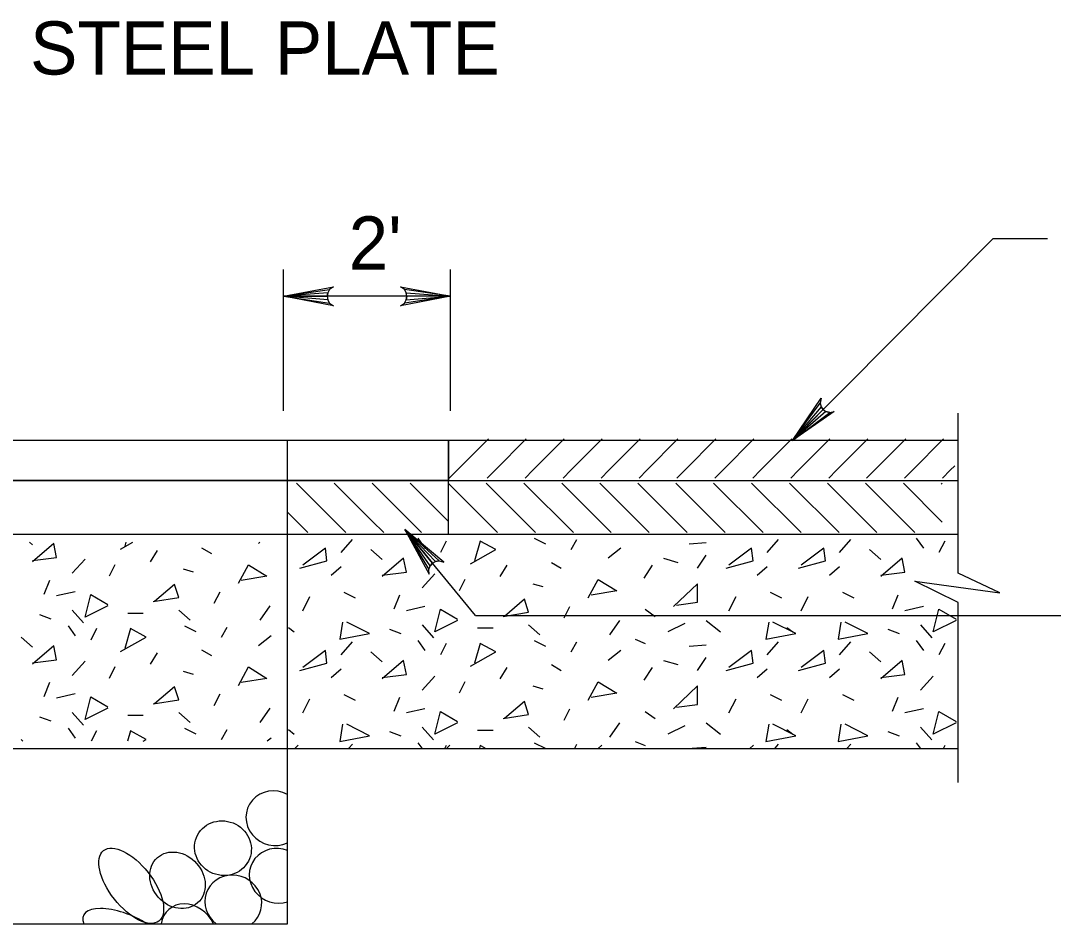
# Model space of a CAD drawing. Extents: x 3.47 to 10.73, y 1.11 to 10.92.
# Drawn here: x 7.328 to 8.494, y 8.665 to 9.69 of the extents above; entities that cross this region are included whole.
import ezdxf

# ---------------------------------------------------------------- set-up
doc = ezdxf.new("R2010")
doc.units = 0
for name, color, linetype in [('DETL-DIMS', 7, 'Continuous'), ('DETL-LINE', 7, 'Continuous'), ('DETL-NOTE', 7, 'Continuous'), ('DETL-PATT', 7, 'Continuous')]:
    doc.layers.add(name, color=color, linetype=linetype)

msp = doc.modelspace()

# ---------------------------------------------------------------- linework, layer by layer
at = {"layer": 'DETL-DIMS'}
for p, q in [((8.4258, 9.4439), (8.1994, 9.2162)), ((8.4877, 9.4439), (8.4258, 9.4439)), ((7.6246, 9.2497), (7.6246, 9.4093)), ((7.8132, 9.2497), (7.8132, 9.4093)), ((7.8132, 9.379), (7.6246, 9.379)), ((7.8415, 9.0184), (7.7615, 9.1157)), ((7.8415, 9.0184), (8.513, 9.0184))]:
    msp.add_line(p, q, dxfattribs=at)
for points in [[(7.6246, 9.379), (7.6811, 9.3896), (7.6767, 9.3866), (7.6745, 9.3828), (7.6738, 9.379), (7.6745, 9.3752), (7.6767, 9.3714), (7.6811, 9.3684), (7.6246, 9.379), (7.6767, 9.3714), (7.6745, 9.3752), (7.6246, 9.379), (7.6738, 9.379), (7.6745, 9.3828), (7.6246, 9.379), (7.6767, 9.3866)], [(7.8132, 9.379), (7.7567, 9.3684), (7.7611, 9.3714), (7.7633, 9.3752), (7.764, 9.379), (7.7633, 9.3828), (7.7611, 9.3866), (7.7567, 9.3896), (7.8132, 9.379), (7.7611, 9.3866), (7.7633, 9.3828), (7.8132, 9.379), (7.764, 9.379), (7.7633, 9.3752), (7.8132, 9.379), (7.7611, 9.3714)], [(8.1994, 9.2162), (8.2318, 9.2638), (8.2308, 9.2585), (8.2319, 9.2543), (8.2342, 9.2512), (8.2373, 9.2489), (8.2416, 9.2479), (8.2468, 9.2488), (8.1994, 9.2162), (8.2416, 9.2479), (8.2373, 9.2489), (8.1994, 9.2162), (8.2342, 9.2512), (8.2319, 9.2543), (8.1994, 9.2162), (8.2308, 9.2585)], [(7.7615, 9.1157), (7.7892, 9.0653), (7.7888, 9.0706), (7.7903, 9.0747), (7.7928, 9.0776), (7.7961, 9.0795), (7.8005, 9.0802), (7.8056, 9.0788), (7.7615, 9.1157), (7.8005, 9.0802), (7.7961, 9.0795), (7.7615, 9.1157), (7.7928, 9.0776), (7.7903, 9.0747), (7.7615, 9.1157), (7.7888, 9.0706)]]:
    msp.add_lwpolyline(points, dxfattribs=at)
at = {"layer": 'DETL-LINE'}
for p, q in [((8.3867, 9.0665), (8.3867, 9.2469)), ((5.5382, 9.2166), (8.3867, 9.2166)), ((7.6291, 9.2166), (8.3867, 9.2166)), ((7.6291, 9.1105), (7.6291, 9.2166)), ((7.811, 9.1105), (7.811, 9.2166)), ((5.5382, 9.1711), (8.3867, 9.1711)), ((5.5382, 9.1105), (8.3867, 9.1105)), ((7.6291, 8.6704), (7.6291, 9.1105)), ((8.3867, 8.83), (8.3867, 9.0332)), ((6.2958, 8.8681), (7.6291, 8.8681)), ((6.2958, 8.8681), (7.6291, 8.8681)), ((7.6291, 8.8681), (8.3867, 8.8681)), ((6.2958, 8.6704), (7.6291, 8.6704))]:
    msp.add_line(p, q, dxfattribs=at)
msp.add_lwpolyline([(6.114, 9.2166), (7.811, 9.2166), (7.811, 9.1711), (6.114, 9.1711)], close=True, dxfattribs=at)
msp.add_lwpolyline([(8.3867, 9.0332), (8.3376, 9.0572), (8.4337, 9.0442), (8.3867, 9.0665)], dxfattribs=at)
at = {"layer": 'DETL-PATT'}
for p, q in [((7.8207, 9.1826), (7.856, 9.2179)), ((7.8636, 9.1826), (7.8988, 9.2179)), ((7.9064, 9.1826), (7.9417, 9.2179)), ((7.9493, 9.1826), (7.9845, 9.2179)), ((7.9921, 9.1826), (8.0274, 9.2179)), ((8.035, 9.1826), (8.0702, 9.2179)), ((8.0778, 9.1826), (8.1131, 9.2179)), ((8.1207, 9.1826), (8.156, 9.2179)), ((8.1636, 9.1826), (8.1988, 9.2179)), ((8.2064, 9.1826), (8.2417, 9.2179)), ((8.2493, 9.1826), (8.2845, 9.2179)), ((8.2921, 9.1826), (8.3274, 9.2179)), ((8.335, 9.1826), (8.3702, 9.2179)), ((7.8119, 9.1738), (7.8207, 9.1826)), ((7.8548, 9.1738), (7.8636, 9.1826)), ((7.8976, 9.1738), (7.9064, 9.1826)), ((7.9405, 9.1738), (7.9493, 9.1826)), ((7.9833, 9.1738), (7.9921, 9.1826)), ((8.0262, 9.1738), (8.035, 9.1826)), ((8.069, 9.1738), (8.0778, 9.1826)), ((8.1119, 9.1738), (8.1207, 9.1826)), ((8.1547, 9.1738), (8.1636, 9.1826)), ((8.1976, 9.1738), (8.2064, 9.1826)), ((8.2405, 9.1738), (8.2493, 9.1826)), ((8.2833, 9.1738), (8.2921, 9.1826)), ((8.3262, 9.1738), (8.335, 9.1826)), ((8.369, 9.1738), (8.3778, 9.1826)), ((8.3778, 9.1826), (8.3829, 9.1877)), ((7.6949, 9.1121), (7.6391, 9.168)), ((7.7248, 9.1251), (7.682, 9.168)), ((7.7806, 9.1121), (7.7248, 9.168)), ((7.811, 9.1247), (7.7677, 9.168)), ((7.8664, 9.1121), (7.8105, 9.168)), ((7.9092, 9.1121), (7.8534, 9.168)), ((7.9521, 9.1121), (7.8962, 9.168)), ((7.9949, 9.1121), (7.9391, 9.168)), ((8.0378, 9.1121), (7.982, 9.168)), ((8.0806, 9.1121), (8.0248, 9.168)), ((8.1235, 9.1121), (8.0677, 9.168)), ((8.1663, 9.1121), (8.1105, 9.168)), ((8.2092, 9.1121), (8.1534, 9.168)), ((8.2521, 9.1121), (8.1962, 9.168)), ((8.2949, 9.1121), (8.2391, 9.168)), ((8.3248, 9.1251), (8.2819, 9.168)), ((8.3688, 9.1239), (8.3248, 9.168)), ((8.3688, 9.1668), (8.3677, 9.168)), ((7.6521, 9.1121), (7.6291, 9.1351)), ((7.7378, 9.1121), (7.7248, 9.1251)), ((8.3378, 9.1121), (8.3248, 9.1251)), ((7.3377, 9.1012), (7.341, 9.0983)), ((7.4405, 9.0935), (7.4544, 9.1012)), ((7.4466, 9.1012), (7.4453, 9.0967)), ((7.5978, 9.1012), (7.5962, 9.1)), ((7.6897, 9.0897), (7.7025, 9.1042)), ((7.7763, 9.1058), (7.7844, 9.0945)), ((7.8084, 9.1026), (7.802, 9.0897)), ((7.9079, 9.1058), (7.9207, 9.0993)), ((7.9496, 9.0929), (7.9561, 9.1042)), ((8.0828, 9.0993), (8.1021, 9.101)), ((8.1711, 9.0897), (8.1839, 9.1042)), ((8.2527, 9.0897), (8.2656, 9.1042)), ((8.3394, 9.1058), (8.3474, 9.0945)), ((8.3715, 9.1026), (8.365, 9.0897)), ((7.4742, 9.0791), (7.4823, 9.0919)), ((7.532, 9.0951), (7.5432, 9.0887)), ((7.7234, 9.0929), (7.7362, 9.0817)), ((8.0058, 9.0945), (7.9914, 9.0833)), ((8.2864, 9.0929), (8.2993, 9.0817)), ((7.4004, 9.0823), (7.386, 9.0663)), ((7.4341, 9.0759), (7.4277, 9.063)), ((7.9272, 9.0785), (7.9384, 9.0721)), ((8.0539, 9.0833), (8.07, 9.0785)), ((8.0924, 9.0721), (8.1021, 9.0865)), ((7.5111, 9.0711), (7.5224, 9.0679)), ((7.6785, 9.064), (7.6897, 9.0737)), ((7.7956, 9.0656), (7.7812, 9.0496)), ((7.8694, 9.0624), (7.8774, 9.0753)), ((8.0411, 9.0753), (8.0315, 9.0608)), ((8.1598, 9.064), (8.1711, 9.0737)), ((8.2415, 9.064), (8.2527, 9.0737)), ((7.3603, 9.0582), (7.3539, 9.0422)), ((7.8293, 9.0592), (7.8229, 9.0464)), ((7.9063, 9.0544), (7.9175, 9.0512)), ((7.3892, 9.0454), (7.3683, 9.0406)), ((7.5464, 9.0326), (7.5529, 9.0454)), ((7.6929, 9.0448), (7.7057, 9.0384)), ((7.7555, 9.0416), (7.7491, 9.0255)), ((8.1743, 9.0448), (8.1871, 9.0384)), ((8.2559, 9.0448), (8.2688, 9.0384)), ((8.3185, 9.0416), (8.3121, 9.0255)), ((7.609, 9.0293), (7.5978, 9.0133)), ((7.6464, 9.0239), (7.6544, 9.04)), ((8.1277, 9.0239), (8.1358, 9.04)), ((8.2094, 9.0239), (8.2174, 9.04)), ((7.3491, 9.0197), (7.3619, 9.0149)), ((7.386, 9.0245), (7.3988, 9.0101)), ((7.4486, 9.0213), (7.4662, 9.0213)), ((7.5063, 9.0245), (7.5192, 9.0133)), ((7.7844, 9.0287), (7.7635, 9.0239)), ((7.9416, 9.0159), (7.948, 9.0287)), ((8.0331, 9.0255), (8.0443, 9.0175)), ((8.3474, 9.0287), (8.3265, 9.0239)), ((7.3812, 9.0069), (7.3892, 8.9957)), ((7.5127, 9.0069), (7.5256, 9.0005)), ((7.7812, 9.0079), (7.794, 8.9934)), ((7.9015, 9.0079), (7.9143, 8.9967)), ((8.0042, 9.0127), (7.993, 8.9967)), ((8.078, 9.0095), (8.0587, 8.9999)), ((8.1021, 9.0127), (8.1181, 8.9999)), ((8.3442, 9.0079), (8.357, 8.9934)), ((7.4133, 9.0037), (7.4068, 8.9908)), ((7.5545, 8.994), (7.5609, 9.0053)), ((7.6106, 8.9957), (7.5962, 8.9844)), ((7.6302, 9.0051), (7.6367, 8.9999)), ((7.7442, 9.0031), (7.7571, 8.9983)), ((7.8437, 9.0047), (7.8614, 9.0047)), ((8.1932, 9.0051), (8.1998, 8.9999)), ((8.3073, 9.0031), (8.3201, 8.9983)), ((7.3282, 8.994), (7.341, 8.9828)), ((7.6897, 8.9742), (7.7025, 8.9886)), ((7.7763, 8.9902), (7.7844, 8.979)), ((7.8084, 8.987), (7.802, 8.9742)), ((7.9079, 8.9902), (7.9207, 8.9838)), ((7.9496, 8.9774), (7.9561, 8.9886)), ((8.0218, 8.9918), (8.0331, 8.987)), ((8.0828, 8.9838), (8.1021, 8.9854)), ((8.1711, 8.9742), (8.1839, 8.9886)), ((8.2527, 8.9742), (8.2656, 8.9886)), ((8.3394, 8.9902), (8.3474, 8.979)), ((8.3715, 8.987), (8.365, 8.9742)), ((7.4742, 8.9636), (7.4823, 8.9764)), ((7.532, 8.9796), (7.5432, 8.9732)), ((7.7234, 8.9774), (7.7362, 8.9662)), ((8.0058, 8.979), (7.9914, 8.9678)), ((8.0924, 8.9565), (8.1021, 8.971)), ((8.2864, 8.9774), (8.2993, 8.9662)), ((7.4004, 8.9668), (7.386, 8.9507)), ((7.4341, 8.9604), (7.4277, 8.9475)), ((7.8694, 8.9469), (7.8774, 8.9597)), ((7.9272, 8.963), (7.9384, 8.9565)), ((8.0411, 8.9597), (8.0315, 8.9453)), ((8.0539, 8.9678), (8.07, 8.963)), ((7.5111, 8.9555), (7.5224, 8.9523)), ((7.6785, 8.9485), (7.6897, 8.9581)), ((7.7956, 8.9501), (7.7812, 8.9341)), ((8.1598, 8.9485), (8.1711, 8.9581)), ((8.2415, 8.9485), (8.2527, 8.9581)), ((8.3586, 8.9501), (8.3442, 8.9341)), ((7.3603, 8.9427), (7.3539, 8.9267)), ((7.8293, 8.9437), (7.8229, 8.9309)), ((7.9063, 8.9389), (7.9175, 8.9357)), ((7.3892, 8.9299), (7.3683, 8.9251)), ((7.5464, 8.917), (7.5529, 8.9299)), ((7.6464, 8.9084), (7.6544, 8.9244)), ((7.6929, 8.9293), (7.7057, 8.9228)), ((7.7555, 8.926), (7.7491, 8.91)), ((8.1277, 8.9084), (8.1358, 8.9244)), ((8.1743, 8.9293), (8.1871, 8.9228)), ((8.2094, 8.9084), (8.2174, 8.9244)), ((8.2559, 8.9293), (8.2688, 8.9228)), ((8.3185, 8.926), (8.3121, 8.91)), ((7.609, 8.9138), (7.5978, 8.8978)), ((7.7844, 8.9132), (7.7635, 8.9084)), ((7.9416, 8.9004), (7.948, 8.9132)), ((8.3474, 8.9132), (8.3265, 8.9084)), ((7.3491, 8.9042), (7.3619, 8.8994)), ((7.386, 8.909), (7.3988, 8.8946)), ((7.4486, 8.9058), (7.4662, 8.9058)), ((7.5063, 8.909), (7.5192, 8.8978)), ((8.0331, 8.91), (8.0443, 8.902)), ((7.3812, 8.8914), (7.3892, 8.8801)), ((7.5127, 8.8914), (7.5256, 8.8849)), ((7.5545, 8.8785), (7.5609, 8.8897)), ((7.6302, 8.8896), (7.6367, 8.8843)), ((7.7812, 8.8924), (7.794, 8.8779)), ((7.9015, 8.8924), (7.9143, 8.8811)), ((8.0042, 8.8972), (7.993, 8.8811)), ((8.078, 8.894), (8.0587, 8.8843)), ((8.1021, 8.8972), (8.1181, 8.8843)), ((8.1932, 8.8896), (8.1998, 8.8843)), ((8.3442, 8.8924), (8.357, 8.8779)), ((7.3282, 8.8785), (7.3303, 8.8767)), ((7.4133, 8.8881), (7.4075, 8.8767)), ((7.6106, 8.8801), (7.6062, 8.8767)), ((7.7442, 8.8875), (7.7571, 8.8827)), ((7.8437, 8.8891), (7.8614, 8.8891)), ((8.3073, 8.8875), (8.3201, 8.8827)), ((7.6372, 8.8681), (7.6411, 8.872)), ((7.6985, 8.8686), (7.7025, 8.8731)), ((7.7763, 8.8747), (7.7807, 8.8686)), ((7.8084, 8.8715), (7.807, 8.8686)), ((7.8087, 8.8681), (7.8126, 8.872)), ((7.9079, 8.8747), (7.9202, 8.8686)), ((7.9535, 8.8686), (7.9561, 8.8731)), ((7.9801, 8.8681), (7.984, 8.872)), ((8.0218, 8.8763), (8.0331, 8.8715)), ((8.0864, 8.8686), (8.1021, 8.8699)), ((8.1515, 8.8681), (8.1554, 8.872)), ((8.1799, 8.8686), (8.1839, 8.8731)), ((8.2615, 8.8686), (8.2656, 8.8731)), ((8.3394, 8.8747), (8.3437, 8.8686)), ((8.3715, 8.8715), (8.37, 8.8686))]:
    msp.add_line(p, q, dxfattribs=at)
for points in [[(7.341, 9.0807), (7.3683, 9.0839), (7.3651, 9.1), (7.341, 9.0791)], [(7.8357, 9.0769), (7.8646, 9.0929), (7.8469, 9.1026), (7.8405, 9.0801)], [(7.6432, 9.0721), (7.6736, 9.0801), (7.672, 9.0945), (7.6464, 9.0753)], [(8.1245, 9.0721), (8.155, 9.0801), (8.1534, 9.0945), (8.1277, 9.0753)], [(8.2062, 9.0721), (8.2367, 9.0801), (8.2351, 9.0945), (8.2094, 9.0753)], [(7.5737, 9.055), (7.5849, 9.0759), (7.6058, 9.063), (7.5769, 9.0582)], [(7.7362, 9.064), (7.7635, 9.0673), (7.7603, 9.0833), (7.7362, 9.0624)], [(8.2993, 9.064), (8.3265, 9.0673), (8.3233, 9.0833), (8.2993, 9.0624)], [(7.4774, 9.0342), (7.5063, 9.039), (7.5015, 9.0534), (7.479, 9.0342)], [(7.9689, 9.0384), (7.9801, 9.0592), (8.001, 9.0464), (7.9721, 9.0416)], [(8.0684, 9.0303), (8.0924, 9.0336), (8.0924, 9.0544), (8.0652, 9.0287)], [(7.4261, 9.0293), (7.4004, 9.0165), (7.4068, 9.0422), (7.4261, 9.031)], [(7.8726, 9.0175), (7.9015, 9.0223), (7.8967, 9.0368), (7.8742, 9.0175)], [(7.8213, 9.0127), (7.7956, 8.9999), (7.802, 9.0255), (7.8213, 9.0143)], [(8.3843, 9.0127), (8.3586, 8.9999), (8.365, 9.0255), (8.3843, 9.0143)], [(7.6913, 9.0111), (7.6881, 8.9918), (7.7218, 8.9983), (7.6961, 9.0111)], [(8.1727, 9.0111), (8.1695, 8.9918), (8.2032, 8.9983), (8.1775, 9.0111)], [(8.2543, 9.0111), (8.2511, 8.9918), (8.2848, 8.9983), (8.2591, 9.0111)], [(7.4405, 8.978), (7.4694, 8.994), (7.4518, 9.0037), (7.4453, 8.9812)], [(7.341, 8.9652), (7.3683, 8.9684), (7.3651, 8.9844), (7.341, 8.9636)], [(7.8357, 8.9614), (7.8646, 8.9774), (7.8469, 8.987), (7.8405, 8.9646)], [(7.6432, 8.9565), (7.6736, 8.9646), (7.672, 8.979), (7.6464, 8.9597)], [(8.1245, 8.9565), (8.155, 8.9646), (8.1534, 8.979), (8.1277, 8.9597)], [(8.2062, 8.9565), (8.2367, 8.9646), (8.2351, 8.979), (8.2094, 8.9597)], [(7.5737, 8.9395), (7.5849, 8.9604), (7.6058, 8.9475), (7.5769, 8.9427)], [(7.7362, 8.9485), (7.7635, 8.9517), (7.7603, 8.9678), (7.7362, 8.9469)], [(8.2993, 8.9485), (8.3265, 8.9517), (8.3233, 8.9678), (8.2993, 8.9469)], [(7.4774, 8.9186), (7.5063, 8.9234), (7.5015, 8.9379), (7.479, 8.9186)], [(7.9689, 8.9228), (7.9801, 8.9437), (8.001, 8.9309), (7.9721, 8.926)], [(8.0684, 8.9148), (8.0924, 8.918), (8.0924, 8.9389), (8.0652, 8.9132)], [(7.4261, 8.9138), (7.4004, 8.901), (7.4068, 8.9267), (7.4261, 8.9154)], [(7.8726, 8.902), (7.9015, 8.9068), (7.8967, 8.9212), (7.8742, 8.902)], [(7.8213, 8.8972), (7.7956, 8.8843), (7.802, 8.91), (7.8213, 8.8988)], [(8.3843, 8.8972), (8.3586, 8.8843), (8.365, 8.91), (8.3843, 8.8988)], [(7.6913, 8.8956), (7.6881, 8.8763), (7.7218, 8.8827), (7.6961, 8.8956)], [(8.1727, 8.8956), (8.1695, 8.8763), (8.2032, 8.8827), (8.1775, 8.8956)], [(8.2543, 8.8956), (8.2511, 8.8763), (8.2848, 8.8827), (8.2591, 8.8956)], [(7.4661, 8.8767), (7.4694, 8.8785), (7.4518, 8.8881), (7.4485, 8.8767)], [(7.8523, 8.8686), (7.8469, 8.8715), (7.8461, 8.8686)]]:
    msp.add_lwpolyline(points, dxfattribs=at)
for centre, major_axis, ratio, start_param, end_param in [((7.6143, 8.7895), (-0.03, 0.012), 0.948581, 4.594923, 8.696661), ((7.618, 8.7245), (-0.03, 0.012), 0.948581, 4.719373, 8.572212), ((7.5679, 8.6944), (-0.03, 0.012), 0.948581, 2.649322, 7.573475), ((7.5175, 8.6608), (-0.0227, 0.0256), 0.844245, 4.37248, 6.906237), ((7.4449, 8.6598), (0.0464, -0.0197), 0.422273, 1.177599, 3.53942)]:
    msp.add_ellipse(centre, major_axis=major_axis, ratio=ratio, start_param=start_param, end_param=end_param, dxfattribs=at)
for centre, major_axis, ratio in [((7.5562, 8.7557), (-0.03, 0.012), 0.948581), ((7.4526, 8.7132), (0.0313, -0.0398), 0.479042), ((7.5048, 8.7194), (-0.0227, 0.0256), 0.844245)]:
    msp.add_ellipse(centre, major_axis=major_axis, ratio=ratio, dxfattribs=at)

# ---------------------------------------------------------------- texts
at = {"layer": 'DETL-NOTE'}
for s, p in [('STEEL PLATE', (7.3383, 9.6295)), ("2'", (7.6982, 9.4093))]:
    msp.add_text(s, height=0.06, dxfattribs=at).set_placement(p)

doc.saveas('drawing.dxf')
